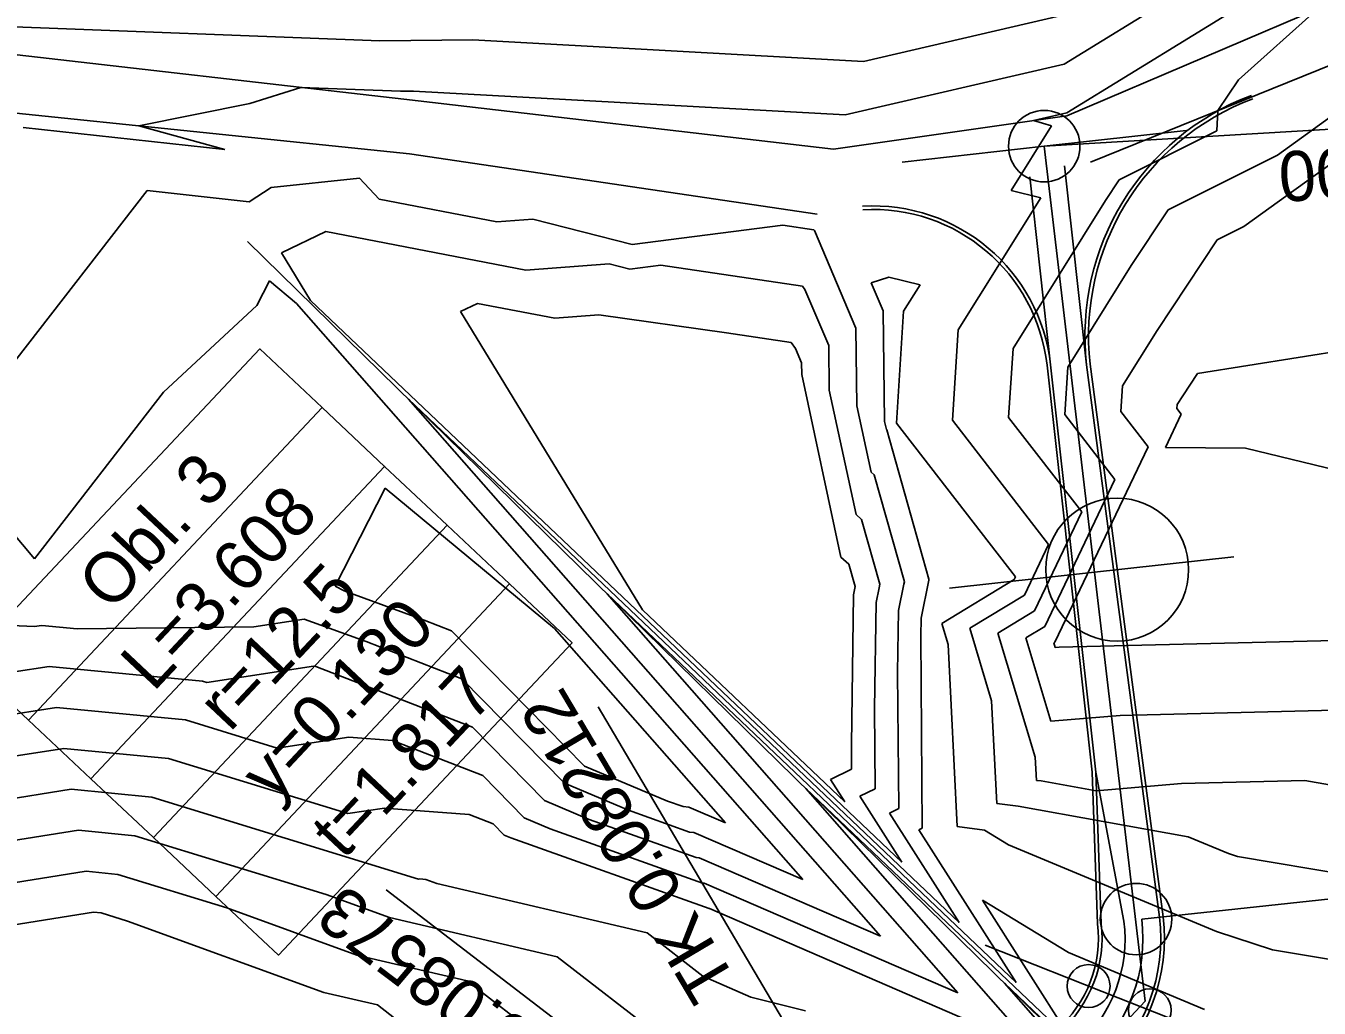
# Model space of a CAD drawing. Extents: x -549394 to -546608, y -1037055 to -1033629.
# Drawn here: x -547906.5 to -547816, y -1035607.2 to -1035538.5 of the extents above; entities that cross this region are included whole.
import ezdxf

# ---------------------------------------------------------------- set-up
doc = ezdxf.new("R2010")
doc.units = 0
for name, color, linetype in [('hlavni_vrst', 7, 'Continuous'), ('hrana_L', 7, 'Continuous'), ('norm_vrst', 7, 'Continuous'), ('POLYGONY_SITUACE_PO', 7, 'Continuous'), ('u_sirka_6m', 7, 'Continuous'), ('x_navrh_C111', 7, 'Continuous'), ('x_osa_C111', 7, 'Continuous'), ('x_popis_oblouky_C111', 7, 'Continuous'), ('x_popis_pricne_rezy_C111', 7, 'Continuous')]:
    doc.layers.add(name, color=color, linetype=linetype)

msp = doc.modelspace()

# ---------------------------------------------------------------- linework, layer by layer
at = {"layer": 'hlavni_vrst'}
for p, q in [((-547833.671, -1035544.616), (-547816.242, -1035533.916)), ((-547835.993, -1035545.154), (-547833.671, -1035544.616)), ((-547837.566, -1035550.059), (-547834.738, -1035545.537)), ((-547834.738, -1035545.537), (-547835.993, -1035545.154)), ((-547889.333, -1035549.833), (-547883.163, -1035549.181)), ((-547883.163, -1035549.181), (-547881.768, -1035550.668)), ((-547907.277, -1035561.996), (-547898.011, -1035550.059)), ((-547898.011, -1035550.059), (-547890.876, -1035550.836)), ((-547890.876, -1035550.836), (-547889.333, -1035549.833)), ((-547835.475, -1035550.557), (-547837.566, -1035550.059)), ((-547881.768, -1035550.668), (-547873.553, -1035552.25)), ((-547841.254, -1035559.801), (-547835.475, -1035550.557)), ((-547873.553, -1035552.25), (-547871.029, -1035552.064)), ((-547871.029, -1035552.064), (-547864.064, -1035553.836)), ((-547864.064, -1035553.836), (-547853.521, -1035552.482)), ((-547853.521, -1035552.482), (-547851.355, -1035552.803)), ((-547851.355, -1035552.803), (-547851.317, -1035552.854)), ((-547851.317, -1035552.854), (-547848.418, -1035559.687)), ((-547848.418, -1035559.687), (-547848.345, -1035565.112)), ((-547841.663, -1035566.127), (-547841.254, -1035559.801)), ((-547879.728, -1035564.658), (-547846.707, -1035602.212)), ((-547841.2, -1035601.241), (-547879.728, -1035564.658)), ((-547848.345, -1035565.112), (-547847.349, -1035569.751)), ((-547834.933, -1035574.809), (-547841.663, -1035566.127)), ((-547847.349, -1035569.751), (-547847.143, -1035569.933)), ((-547847.143, -1035569.933), (-547845.031, -1035577.414)), ((-547836.627, -1035578.352), (-547834.933, -1035574.809)), ((-547845.062, -1035577.578), (-547845.436, -1035579.422)), ((-547845.031, -1035577.414), (-547845.062, -1035577.578)), ((-547840.457, -1035580.669), (-547836.627, -1035578.352)), ((-547845.436, -1035579.422), (-547845.502, -1035583.757)), ((-547838.922, -1035585.752), (-547840.457, -1035580.669)), ((-547904.861, -1035583.338), (-547907.323, -1035583.728)), ((-547894.149, -1035584.375), (-547904.861, -1035583.338)), ((-547886.371, -1035583.327), (-547893.843, -1035584.469)), ((-547886.198, -1035583.341), (-547886.371, -1035583.327)), ((-547875.255, -1035587.598), (-547886.198, -1035583.341)), ((-547893.843, -1035584.469), (-547894.149, -1035584.375)), ((-547845.502, -1035583.757), (-547845.426, -1035593.287)), ((-547838.569, -1035592.92), (-547838.922, -1035585.752)), ((-547870.216, -1035592.723), (-547875.255, -1035587.598)), ((-547867.078, -1035594.049), (-547870.216, -1035592.723)), ((-547845.426, -1035593.287), (-547846.073, -1035593.596)), ((-547846.073, -1035593.596), (-547841.2, -1035601.241)), ((-547837.061, -1035593.123), (-547838.569, -1035592.92)), ((-547825.174, -1035595.254), (-547837.061, -1035593.123)), ((-547859.604, -1035596.71), (-547867.078, -1035594.049)), ((-547822.341, -1035596.435), (-547825.174, -1035595.254)), ((-547859.39, -1035596.725), (-547859.604, -1035596.71)), ((-547846.707, -1035602.212), (-547859.39, -1035596.725)), ((-547821.716, -1035596.638), (-547822.341, -1035596.435)), ((-547805.21, -1035599.429), (-547821.716, -1035596.638)), ((-547902.289, -1035597.667), (-547914.368, -1035599.581)), ((-547900.052, -1035597.884), (-547902.289, -1035597.667)), ((-547892.442, -1035600.223), (-547900.052, -1035597.884)), ((-547883.348, -1035603.526), (-547892.442, -1035600.223)), ((-547875.613, -1035605.342), (-547883.348, -1035603.526)), ((-547860.696, -1035616.846), (-547875.613, -1035605.342))]:
    msp.add_line(p, q, dxfattribs=at)
at = {"layer": 'hrana_L'}
for p, q in [((-547814.39, -1035536.61), (-547833.66, -1035544.82)), ((-547880.04, -1035543.67), (-547909.34, -1035540.3)), ((-547832.01, -1035548.06), (-547813.58, -1035540.62)), ((-547849.99, -1035547.16), (-547880.04, -1035543.67)), ((-547909.02, -1035544.46), (-547879.65, -1035547.5)), ((-547833.66, -1035544.82), (-547849.99, -1035547.16)), ((-547851.13, -1035551.7), (-547879.65, -1035547.5)), ((-547890.99, -1035553.63), (-547825.64, -1035617.62))]:
    msp.add_line(p, q, dxfattribs=at)
at = {"layer": 'norm_vrst'}
for p, q in [((-547833.854, -1035541.213), (-547817.942, -1035531.445)), ((-547821.638, -1035542.305), (-547816.074, -1035537.327)), ((-547847.895, -1035541.024), (-547834.036, -1035537.811)), ((-547908.8, -1035538.552), (-547881.735, -1035539.584)), ((-547881.735, -1035539.584), (-547875.218, -1035539.515)), ((-547875.218, -1035539.515), (-547847.895, -1035541.024)), ((-547849.172, -1035544.766), (-547833.854, -1035541.213)), ((-547890.823, -1035543.964), (-547887.252, -1035542.84)), ((-547887.252, -1035542.84), (-547880.274, -1035543.106)), ((-547823.097, -1035544.462), (-547821.638, -1035542.305)), ((-547880.274, -1035543.106), (-547879.375, -1035543.097)), ((-547879.375, -1035543.097), (-547849.172, -1035544.766)), ((-547898.586, -1035545.54), (-547890.823, -1035543.964)), ((-547823.16, -1035545.882), (-547823.097, -1035544.462)), ((-547821.285, -1035552.58), (-547810.316, -1035544.669)), ((-547818.924, -1035547.58), (-547814.726, -1035544.552)), ((-547906.68, -1035545.65), (-547892.568, -1035547.187)), ((-547892.568, -1035547.187), (-547898.586, -1035545.54)), ((-547829.989, -1035549.301), (-547823.16, -1035545.882)), ((-547826.562, -1035551.404), (-547818.924, -1035547.58)), ((-547830.949, -1035550.746), (-547829.989, -1035549.301)), ((-547837.425, -1035561.107), (-547830.949, -1035550.746)), ((-547829.15, -1035555.299), (-547826.562, -1035551.404)), ((-547888.611, -1035554.411), (-547885.5, -1035552.926)), ((-547885.5, -1035552.926), (-547871.518, -1035555.619)), ((-547823.136, -1035553.507), (-547821.285, -1035552.58)), ((-547827.351, -1035559.852), (-547823.136, -1035553.507)), ((-547886.578, -1035557.741), (-547888.611, -1035554.411)), ((-547871.518, -1035555.619), (-547865.673, -1035555.188)), ((-547865.673, -1035555.188), (-547864.235, -1035555.553)), ((-547864.235, -1035555.553), (-547862.06, -1035555.274)), ((-547862.06, -1035555.274), (-547852.157, -1035556.74)), ((-547833.596, -1035562.412), (-547829.15, -1035555.299)), ((-547890.328, -1035558.105), (-547889.451, -1035556.382)), ((-547889.451, -1035556.382), (-547887.56, -1035557.949)), ((-547846.122, -1035556.125), (-547847.352, -1035556.502)), ((-547847.352, -1035556.502), (-547846.516, -1035558.473)), ((-547843.927, -1035556.647), (-547846.122, -1035556.125)), ((-547852.157, -1035556.74), (-547851.987, -1035556.976)), ((-547851.987, -1035556.976), (-547850.321, -1035560.901)), ((-547845.083, -1035558.496), (-547843.927, -1035556.647)), ((-547896.864, -1035564.157), (-547890.328, -1035558.105)), ((-547887.56, -1035557.949), (-547852.122, -1035598.251)), ((-547845.2, -1035597.03), (-547886.578, -1035557.741)), ((-547876.089, -1035558.521), (-547874.887, -1035557.947)), ((-547874.887, -1035557.947), (-547869.482, -1035558.988)), ((-547863.356, -1035579.379), (-547876.089, -1035558.521)), ((-547869.482, -1035558.988), (-547866.397, -1035558.76)), ((-547866.397, -1035558.76), (-547857.465, -1035560.011)), ((-547846.516, -1035558.473), (-547846.411, -1035566.207)), ((-547845.59, -1035566.331), (-547845.083, -1035558.496)), ((-547857.465, -1035560.011), (-547852.959, -1035560.678)), ((-547829.767, -1035563.717), (-547827.351, -1035559.852)), ((-547852.959, -1035560.678), (-547852.656, -1035561.097)), ((-547850.321, -1035560.901), (-547850.279, -1035564.018)), ((-547824.518, -1035562.848), (-547809.54, -1035560.474)), ((-547852.656, -1035561.097), (-547852.224, -1035562.115)), ((-547837.737, -1035565.922), (-547837.425, -1035561.107)), ((-547852.224, -1035562.115), (-547852.213, -1035562.923)), ((-547833.81, -1035565.718), (-547833.596, -1035562.412)), ((-547825.552, -1035564.405), (-547824.518, -1035562.848)), ((-547852.213, -1035562.923), (-547849.471, -1035575.7)), ((-547829.883, -1035565.513), (-547829.767, -1035563.717)), ((-547905.904, -1035575.804), (-547896.864, -1035564.157)), ((-547850.279, -1035564.018), (-547848.41, -1035572.726)), ((-547825.938, -1035565.022), (-547825.552, -1035564.405)), ((-547915.122, -1035564.83), (-547905.904, -1035575.804)), ((-547827.972, -1035567.979), (-547829.883, -1035565.513)), ((-547825.956, -1035565.309), (-547825.938, -1035565.022)), ((-547825.651, -1035565.703), (-547825.956, -1035565.309)), ((-547846.411, -1035566.207), (-547846.289, -1035566.776)), ((-547837.254, -1035577.086), (-547845.59, -1035566.331)), ((-547832.613, -1035572.533), (-547837.737, -1035565.922)), ((-547830.292, -1035570.256), (-547833.81, -1035565.718)), ((-547826.765, -1035568.034), (-547825.651, -1035565.703)), ((-547846.289, -1035566.776), (-547846.263, -1035566.799)), ((-547846.263, -1035566.799), (-547843.314, -1035577.249)), ((-547834.502, -1035581.644), (-547827.972, -1035567.979)), ((-547821.155, -1035568.076), (-547826.765, -1035568.034)), ((-547799.426, -1035573.391), (-547821.155, -1035568.076)), ((-547884.847, -1035577.738), (-547881.353, -1035570.868)), ((-547881.353, -1035570.868), (-547869.507, -1035580.678)), ((-547835.211, -1035580.547), (-547830.292, -1035570.256)), ((-547848.41, -1035572.726), (-547848.023, -1035573.067)), ((-547835.919, -1035579.45), (-547832.613, -1035572.533)), ((-547848.023, -1035573.067), (-547846.749, -1035577.579)), ((-547849.471, -1035575.7), (-547848.903, -1035576.2)), ((-547848.903, -1035576.2), (-547848.467, -1035577.744)), ((-547843.326, -1035577.314), (-547843.864, -1035579.967)), ((-547843.314, -1035577.249), (-547843.326, -1035577.314)), ((-547842.417, -1035580.329), (-547837.335, -1035577.255)), ((-547837.335, -1035577.255), (-547837.254, -1035577.086)), ((-547884.221, -1035578.062), (-547884.847, -1035577.738)), ((-547878.627, -1035580.095), (-547884.221, -1035578.062)), ((-547848.534, -1035578.106), (-547848.58, -1035578.333)), ((-547848.467, -1035577.744), (-547848.534, -1035578.106)), ((-547846.798, -1035577.842), (-547847.008, -1035578.877)), ((-547846.749, -1035577.579), (-547846.798, -1035577.842)), ((-547865.823, -1035578.273), (-547841.291, -1035606.173)), ((-547837.2, -1035605.451), (-547865.823, -1035578.273)), ((-547848.58, -1035578.333), (-547848.738, -1035588.817)), ((-547847.008, -1035578.877), (-547847.12, -1035586.287)), ((-547905.915, -1035580.558), (-547921.14, -1035579.807)), ((-547887.027, -1035580.034), (-547890.537, -1035580.58)), ((-547882.696, -1035581.608), (-547887.027, -1035580.034)), ((-547849.2, -1035592.82), (-547863.356, -1035579.379)), ((-547843.864, -1035579.967), (-547843.883, -1035581.227)), ((-547838.497, -1035581.01), (-547835.919, -1035579.45)), ((-547905.376, -1035580.472), (-547905.915, -1035580.558)), ((-547902.918, -1035580.71), (-547905.376, -1035580.472)), ((-547890.537, -1035580.58), (-547902.918, -1035580.71)), ((-547876.709, -1035580.841), (-547878.627, -1035580.095)), ((-547867.399, -1035590.31), (-547876.709, -1035580.841)), ((-547869.507, -1035580.678), (-547857.538, -1035594.29)), ((-547841.97, -1035581.807), (-547842.417, -1035580.329)), ((-547836.537, -1035581.35), (-547835.211, -1035580.547)), ((-547875.982, -1035584.219), (-547882.696, -1035581.608)), ((-547843.883, -1035581.227), (-547843.777, -1035594.663)), ((-547841.344, -1035594.533), (-547841.97, -1035581.807)), ((-547835.874, -1035589.696), (-547838.497, -1035581.01)), ((-547834.777, -1035587.178), (-547836.537, -1035581.35)), ((-547834.578, -1035581.69), (-547834.502, -1035581.644)), ((-547834.478, -1035582.019), (-547834.578, -1035581.69)), ((-547804.251, -1035581.284), (-547834.203, -1035581.996)), ((-547834.203, -1035581.996), (-547834.478, -1035582.019)), ((-547868.808, -1035591.517), (-547875.982, -1035584.219)), ((-547904.347, -1035586.204), (-547908.732, -1035586.899)), ((-547895.33, -1035587.077), (-547904.347, -1035586.204)), ((-547847.12, -1035586.287), (-547847.075, -1035591.911)), ((-547810.631, -1035586.307), (-547829.925, -1035586.766)), ((-547888.905, -1035589.052), (-547895.33, -1035587.077)), ((-547829.925, -1035586.766), (-547834.777, -1035587.178)), ((-547903.833, -1035589.07), (-547910.141, -1035590.069)), ((-547896.51, -1035589.779), (-547903.833, -1035589.07)), ((-547883.891, -1035588.286), (-547888.905, -1035589.052)), ((-547880.835, -1035588.523), (-547883.891, -1035588.286)), ((-547874.529, -1035590.976), (-547880.835, -1035588.523)), ((-547848.738, -1035588.817), (-547848.724, -1035590.535)), ((-547883.966, -1035593.634), (-547896.51, -1035589.779)), ((-547835.795, -1035591.308), (-547835.874, -1035589.696)), ((-547861.601, -1035592.759), (-547867.399, -1035590.31)), ((-547848.724, -1035590.535), (-547850.206, -1035591.242)), ((-547871.625, -1035593.929), (-547874.529, -1035590.976)), ((-547864.339, -1035593.404), (-547868.808, -1035591.517)), ((-547850.206, -1035591.242), (-547849.2, -1035592.82)), ((-547835.456, -1035591.353), (-547835.795, -1035591.308)), ((-547831.613, -1035592.042), (-547835.456, -1035591.353)), ((-547825.646, -1035591.536), (-547831.613, -1035592.042)), ((-547817.012, -1035591.331), (-547825.646, -1035591.536)), ((-547804.583, -1035593.432), (-547817.012, -1035591.331)), ((-547903.318, -1035591.936), (-547911.55, -1035593.24)), ((-547897.691, -1035592.48), (-547903.318, -1035591.936)), ((-547879.028, -1035598.217), (-547897.691, -1035592.48)), ((-547851.919, -1035591.888), (-547835.876, -1035610.134)), ((-547833.2, -1035609.662), (-547851.919, -1035591.888)), ((-547847.075, -1035591.911), (-547848.139, -1035592.419)), ((-547848.139, -1035592.419), (-547845.2, -1035597.03)), ((-547881.41, -1035593.244), (-547883.966, -1035593.634)), ((-547875.471, -1035593.705), (-547881.41, -1035593.244)), ((-547860.059, -1035594.928), (-547864.339, -1035593.404)), ((-547860.515, -1035593.146), (-547861.601, -1035592.759)), ((-547860.115, -1035593.175), (-547860.515, -1035593.146)), ((-547857.538, -1035594.29), (-547860.115, -1035593.175)), ((-547873.802, -1035594.354), (-547875.471, -1035593.705)), ((-547873.033, -1035595.136), (-547873.802, -1035594.354)), ((-547869.816, -1035594.693), (-547871.625, -1035593.929)), ((-547839.415, -1035594.793), (-547841.344, -1035594.533)), ((-547902.804, -1035594.801), (-547912.959, -1035596.41)), ((-547898.871, -1035595.182), (-547902.804, -1035594.801)), ((-547885.497, -1035599.293), (-547898.871, -1035595.182)), ((-547872.554, -1035595.338), (-547873.033, -1035595.136)), ((-547858.692, -1035600.273), (-547872.554, -1035595.338)), ((-547859.148, -1035598.491), (-547869.816, -1035594.693)), ((-547859.753, -1035594.95), (-547860.059, -1035594.928)), ((-547852.122, -1035598.251), (-547859.753, -1035594.95)), ((-547843.777, -1035594.663), (-547844.006, -1035594.773)), ((-547844.006, -1035594.773), (-547837.2, -1035605.451)), ((-547837.74, -1035595.817), (-547839.415, -1035594.793)), ((-547823.189, -1035601.881), (-547837.74, -1035595.817)), ((-547878.929, -1035598.202), (-547879.028, -1035598.217)), ((-547878.519, -1035598.234), (-547878.929, -1035598.202)), ((-547877.749, -1035598.527), (-547878.519, -1035598.234)), ((-547863.028, -1035601.982), (-547877.749, -1035598.527)), ((-547859.028, -1035598.5), (-547859.148, -1035598.491)), ((-547841.291, -1035606.173), (-547859.028, -1035598.5)), ((-547881.043, -1035600.911), (-547885.497, -1035599.293)), ((-547833.553, -1035603.361), (-547839.557, -1035599.689)), ((-547839.557, -1035599.689), (-547833.2, -1035609.662)), ((-547901.775, -1035600.533), (-547908.038, -1035601.525)), ((-547901.232, -1035600.585), (-547901.775, -1035600.533)), ((-547899.388, -1035601.152), (-547901.232, -1035600.585)), ((-547858.665, -1035600.275), (-547858.692, -1035600.273)), ((-547835.876, -1035610.134), (-547858.665, -1035600.275)), ((-547885.653, -1035606.142), (-547899.388, -1035601.152)), ((-547869.32, -1035603.662), (-547881.043, -1035600.911)), ((-547859.12, -1035604.997), (-547863.028, -1035601.982)), ((-547819.274, -1035603.153), (-547823.189, -1035601.881)), ((-547824.037, -1035607.327), (-547833.553, -1035603.361)), ((-547805.836, -1035605.425), (-547819.274, -1035603.153)), ((-547859.908, -1035610.921), (-547869.32, -1035603.662)), ((-547855.766, -1035606.476), (-547859.12, -1035604.997)), ((-547881.905, -1035607.021), (-547885.653, -1035606.142)), ((-547838.015, -1035605.503), (-547830.46, -1035614.095)), ((-547829.2, -1035613.873), (-547838.015, -1035605.503)), ((-547861.484, -1035622.771), (-547881.905, -1035607.021)), ((-547851.957, -1035607.426), (-547855.766, -1035606.476))]:
    msp.add_line(p, q, dxfattribs=at)
at = {"layer": 'POLYGONY_SITUACE_PO'}
for centre in [(-547835.243, -1035546.954), (-547828.818, -1035601.013)]:
    msp.add_circle(centre, 2.5, dxfattribs=at)
at = {"layer": 'u_sirka_6m'}
for centre, radius in [((-547830.139, -1035576.571), 5), ((-547832.139, -1035605.696), 1.5), ((-547827.853, -1035607.388), 1.5)]:
    msp.add_circle(centre, radius, dxfattribs=at)
at = {"layer": 'x_navrh_C111'}
for p, q in [((-547831.878, -1035590.742), (-547835.047, -1035562.276)), ((-547826.931, -1035600.855), (-547832.036, -1035562.208)), ((-547831.515, -1035601.345), (-547831.878, -1035590.742)), ((-547831.265, -1035601.337), (-547831.628, -1035590.735))]:
    msp.add_line(p, q, dxfattribs=at)
for points in [[(-547832.285, -1035562.236), (-547833.833, -1035548.322)], [(-547834.799, -1035562.248), (-547836.261, -1035549.107)], [(-547831.628, -1035590.735), (-547834.799, -1035562.248)], [(-547827.18, -1035600.882), (-547832.285, -1035562.236)], [(-547829.665, -1035601.159), (-547831.628, -1035590.735)]]:
    msp.add_lwpolyline(points, dxfattribs=at)
for centre, radius, start, end in [((-547814.395, -1035560.244), 18, 110.66066, 186.35155), ((-547814.395, -1035560.244), 17.75, 110.66066, 186.35155), ((-547847.222, -1035563.631), 12.5, 6.35155, 93.33925), ((-547847.222, -1035563.631), 12.25, 6.35155, 93.33925)]:
    msp.add_arc(centre, radius, start, end, dxfattribs=at)
for centre, major_axis, ratio, start_param, end_param in [((-547842.326, -1035602.402), (15.239, 0), 0.901672, 5.528124, 6.394041), ((-547842.326, -1035602.402), (15.489, 0), 0.903259, 5.528124, 6.394041), ((-547842.327, -1035602.402), (10.881, 0), 0.862163, 5.528126, 6.396156), ((-547842.326, -1035602.402), (11.129, 0), 0.86536, 5.528126, 6.394041), ((-547842.326, -1035602.402), (12.739, 0), 0.882376, 5.528124, 6.394041)]:
    msp.add_ellipse(centre, major_axis=major_axis, ratio=ratio, start_param=start_param, end_param=end_param, dxfattribs=at)
at = {"layer": 'x_osa_C111'}
for p, q in [((-547828.179, -1035606.755), (-547835.243, -1035546.954)), ((-547840.291, -1035619.626), (-547828.179, -1035606.755))]:
    msp.add_line(p, q, dxfattribs=at)
msp.add_ellipse((-547842.326, -1035602.402), major_axis=(13.989, 0), ratio=0.892887, start_param=5.528124, end_param=6.394041, dxfattribs=at)
at = {"layer": 'x_popis_oblouky_C111'}
for points in [[(-547835.243, -1035546.954), (-547793.942, -1035544.509)], [(-547866.464, -1035586.169), (-547845.095, -1035622.348)], [(-547828.422, -1035601.02), (-547788.086, -1035596.682)], [(-547881.279, -1035598.964), (-547847.935, -1035624.552)]]:
    msp.add_lwpolyline(points, dxfattribs=at)
for points in [[(-547910.687, -1035582.984), (-547890.136, -1035561.129), (-547885.765, -1035565.24), (-547906.316, -1035587.094)], [(-547906.316, -1035587.094), (-547885.765, -1035565.24), (-547881.394, -1035569.35), (-547901.945, -1035591.205)], [(-547901.945, -1035591.205), (-547881.394, -1035569.35), (-547877.023, -1035573.46), (-547897.574, -1035595.315)], [(-547897.574, -1035595.315), (-547877.023, -1035573.46), (-547872.652, -1035577.571), (-547893.203, -1035599.425)], [(-547893.203, -1035599.425), (-547872.652, -1035577.571), (-547868.281, -1035581.681), (-547888.832, -1035603.536)]]:
    msp.add_lwpolyline(points, close=True, dxfattribs=at)
at = {"layer": 'x_popis_pricne_rezy_C111'}
for points in [[(-547825.305, -1035545.848), (-547835.243, -1035546.954), (-547845.182, -1035548.06)], [(-547821.986, -1035575.664), (-547831.924, -1035576.77), (-547841.863, -1035577.876)], [(-547820.776, -1035610.184), (-547830.077, -1035606.51), (-547839.377, -1035602.836)]]:
    msp.add_lwpolyline(points, dxfattribs=at)

# ---------------------------------------------------------------- texts
at = {"layer": 'x_popis_oblouky_C111'}
for s, rotation, p in [('ZÚ 0.00000', 183.70757, (-547794.538, -1035545.786)), ('Obl. 3', 46.78219, (-547900.558, -1035579.59)), ('L=3.608', 46.78219, (-547897.584, -1035585.188)), ('r=12.5', 46.78219, (-547892.22, -1035587.991)), ('y=0.130', 46.78219, (-547889.209, -1035592.903)), ('t=1.817', 46.78219, (-547884.262, -1035596.915)), ('TK 0.08212', 120.67472, (-547856.685, -1035605.435)), ('KT 0.08573', 142.95281, (-547864.955, -1035613.063))]:
    msp.add_text(s, height=3.5, rotation=rotation, dxfattribs=at).set_placement(p)

doc.saveas('drawing.dxf')
